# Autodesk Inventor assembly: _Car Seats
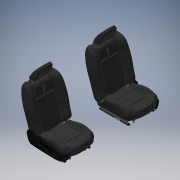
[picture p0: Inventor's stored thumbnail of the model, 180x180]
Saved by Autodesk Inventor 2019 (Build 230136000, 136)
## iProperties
Company: Autodesk Inc.
Created: 2017-07
Part Number: _Car Seats
Document SubType Name: Assembly
Designer: Autodesk Inc.
Mass: 126389 g
Surface Area: 151231 cm^2
Volume: 99144.7 cm^3
Density: 1.27479 g/cm^3
Author: Inventor
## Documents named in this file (3)
- C:\TEMP\Car Seat\Workspace\_Car Seats.iam
- C:\TEMP\Car Seat\Workspace\Car Seat.iam
- C:\TEMP\Car Seat\Workspace\Car Seat_MIR.iam
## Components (2 placed, 2 different names)
1. Car Seat:1 [sub-assembly] — Flush:1, Flush:2, Flush:3
2. Car Seat_MIR:1 [sub-assembly] — Mate:5, Flush:5, Flush:6
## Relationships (6: Flush 5, Mate 1)
- Flush:1: Car Seat:1
- Flush:2: Car Seat:1
- Flush:3: Car Seat:1
- Mate:5: Car Seat_MIR:1
- Flush:5: Car Seat_MIR:1
- Flush:6: Car Seat_MIR:1
